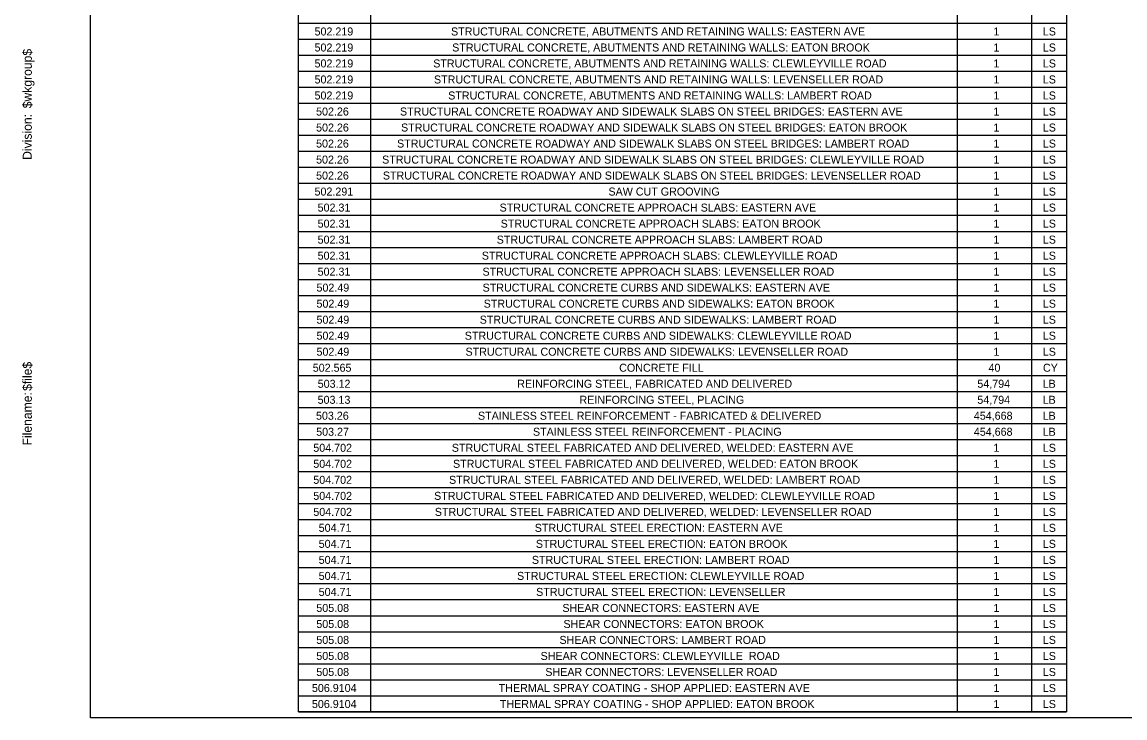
# Model space of a CAD drawing. Extents: x -18.7 to 5.6, y -2.7 to 4.
# Drawn here: x -9.864 to -8.508, y 2.235 to 3.09 of the extents above; entities that cross this region are included whole.
import ezdxf

# ---------------------------------------------------------------- set-up
doc = ezdxf.new("R2010")
doc.units = 0
doc.layers.add('ANNOTATION', color=7, linetype='Continuous')
doc.layers.add('BORDER', color=7, linetype='Continuous')

msp = doc.modelspace()

# ---------------------------------------------------------------- linework, layer by layer
at = {"layer": 'BORDER'}
for p, q in [((-9.4355, 3.9551), (-9.4355, 2.2424)), ((-8.7141, 3.9551), (-8.7141, 2.2424)), ((-8.6227, 3.9551), (-8.6227, 2.2424)), ((-9.524, 3.0889), (-8.5798, 3.0889)), ((-9.524, 3.0692), (-8.5798, 3.0692)), ((-9.524, 3.0495), (-8.5798, 3.0495)), ((-9.524, 3.0299), (-8.5798, 3.0299)), ((-9.524, 3.0102), (-8.5798, 3.0102)), ((-9.524, 2.9905), (-8.5798, 2.9905)), ((-9.524, 2.9708), (-8.5798, 2.9708)), ((-9.524, 2.9511), (-8.5798, 2.9511)), ((-9.524, 2.9314), (-8.5798, 2.9314)), ((-9.524, 2.9117), (-8.5798, 2.9117)), ((-9.524, 2.8921), (-8.5798, 2.8921)), ((-9.524, 2.8724), (-8.5798, 2.8724)), ((-9.524, 2.8527), (-8.5798, 2.8527)), ((-9.524, 2.833), (-8.5798, 2.833)), ((-9.524, 2.8133), (-8.5798, 2.8133)), ((-9.524, 2.7936), (-8.5798, 2.7936)), ((-9.524, 2.7739), (-8.5798, 2.7739)), ((-9.524, 2.7543), (-8.5798, 2.7543)), ((-9.524, 2.7346), (-8.5798, 2.7346)), ((-9.524, 2.7149), (-8.5798, 2.7149)), ((-9.524, 2.6952), (-8.5798, 2.6952)), ((-9.524, 2.6755), (-8.5798, 2.6755)), ((-9.524, 2.6558), (-8.5798, 2.6558)), ((-9.524, 2.6361), (-8.5798, 2.6361)), ((-9.524, 2.6165), (-8.5798, 2.6165)), ((-9.524, 2.5968), (-8.5798, 2.5968)), ((-9.524, 2.5771), (-8.5798, 2.5771)), ((-9.524, 2.5574), (-8.5798, 2.5574)), ((-9.524, 2.5377), (-8.5798, 2.5377)), ((-9.524, 2.518), (-8.5798, 2.518)), ((-9.524, 2.4983), (-8.5798, 2.4983)), ((-9.524, 2.4787), (-8.5798, 2.4787)), ((-9.524, 2.459), (-8.5798, 2.459)), ((-9.524, 2.4393), (-8.5798, 2.4393)), ((-9.524, 2.4196), (-8.5798, 2.4196)), ((-9.524, 2.3999), (-8.5798, 2.3999)), ((-9.524, 2.3802), (-8.5798, 2.3802)), ((-9.524, 2.3605), (-8.5798, 2.3605)), ((-9.524, 2.3408), (-8.5798, 2.3408)), ((-9.524, 2.3212), (-8.5798, 2.3212)), ((-9.524, 2.3015), (-8.5798, 2.3015)), ((-9.524, 2.2818), (-8.5798, 2.2818)), ((-9.524, 2.2621), (-8.5798, 2.2621)), ((-9.524, 2.2424), (-8.5798, 2.2424))]:
    msp.add_line(p, q, dxfattribs=at)
for points in [[(-9.7797, 3.9848), (-7.1131, 3.9848), (-7.1131, 2.2348), (-9.7797, 2.2348)], [(-9.524, 3.9748), (-8.5798, 3.9748), (-8.5798, 2.2424), (-9.524, 2.2424)]]:
    msp.add_lwpolyline(points, close=True, dxfattribs=at)

# ---------------------------------------------------------------- texts
at = {"layer": 'ANNOTATION'}
for s, height, p in [('502.219', 0.00984, (-9.5041, 3.0738)), ('STRUCTURAL CONCRETE, ABUTMENTS AND RETAINING WALLS: EASTERN AVE', 0.009843, (-9.3363, 3.0738)), ('1', 0.00984, (-8.6695, 3.0738)), ('LS', 0.00984, (-8.6088, 3.0738)), ('502.219', 0.00984, (-9.5041, 3.0541)), ('STRUCTURAL CONCRETE, ABUTMENTS AND RETAINING WALLS: EATON BROOK', 0.009843, (-9.3349, 3.0541)), ('LS', 0.00984, (-8.6088, 3.0541)), ('1', 0.00984, (-8.6695, 3.0541)), ('502.219', 0.00984, (-9.5041, 3.0345)), ('STRUCTURAL CONCRETE, ABUTMENTS AND RETAINING WALLS: CLEWLEYVILLE ROAD', 0.009843, (-9.3582, 3.0345)), ('1', 0.00984, (-8.6695, 3.0345)), ('LS', 0.00984, (-8.6088, 3.0345)), ('502.219', 0.00984, (-9.5041, 3.0148)), ('STRUCTURAL CONCRETE, ABUTMENTS AND RETAINING WALLS: LEVENSELLER ROAD', 0.009843, (-9.3573, 3.0148)), ('1', 0.00984, (-8.6695, 3.0148)), ('LS', 0.00984, (-8.6088, 3.0148)), ('502.219', 0.00984, (-9.5041, 2.9951)), ('STRUCTURAL CONCRETE, ABUTMENTS AND RETAINING WALLS: LAMBERT ROAD', 0.009843, (-9.3398, 2.9951)), ('1', 0.00984, (-8.6695, 2.9951)), ('LS', 0.00984, (-8.6088, 2.9951)), ('502.26', 0.00984, (-9.5022, 2.9754)), ('STRUCTURAL CONCRETE ROADWAY AND SIDEWALK SLABS ON STEEL BRIDGES: EASTERN AVE', 0.009843, (-9.3991, 2.9754)), ('1', 0.00984, (-8.6695, 2.9754)), ('LS', 0.00984, (-8.6088, 2.9754)), ('502.26', 0.00984, (-9.5022, 2.9557)), ('STRUCTURAL CONCRETE ROADWAY AND SIDEWALK SLABS ON STEEL BRIDGES: EATON BROOK', 0.009843, (-9.3978, 2.9557)), ('1', 0.00984, (-8.6695, 2.9557)), ('LS', 0.00984, (-8.6088, 2.9557)), ('502.26', 0.00984, (-9.5022, 2.936)), ('STRUCTURAL CONCRETE ROADWAY AND SIDEWALK SLABS ON STEEL BRIDGES: LAMBERT ROAD', 0.009843, (-9.4027, 2.936)), ('1', 0.00984, (-8.6695, 2.936)), ('LS', 0.00984, (-8.6088, 2.936)), ('502.26', 0.00984, (-9.5022, 2.9163)), ('STRUCTURAL CONCRETE ROADWAY AND SIDEWALK SLABS ON STEEL BRIDGES: CLEWLEYVILLE ROAD', 0.009843, (-9.421, 2.9163)), ('1', 0.00984, (-8.6695, 2.9163)), ('LS', 0.00984, (-8.6088, 2.9163)), ('502.26', 0.00984, (-9.5022, 2.8967)), ('STRUCTURAL CONCRETE ROADWAY AND SIDEWALK SLABS ON STEEL BRIDGES: LEVENSELLER ROAD', 0.009843, (-9.4201, 2.8967)), ('1', 0.00984, (-8.6695, 2.8967)), ('LS', 0.00984, (-8.6088, 2.8967)), ('502.291', 0.00984, (-9.5041, 2.877)), ('SAW CUT GROOVING', 0.009843, (-9.1428, 2.877)), ('1', 0.00984, (-8.6695, 2.877)), ('LS', 0.00984, (-8.6088, 2.877)), ('502.31', 0.00984, (-9.5003, 2.8573)), ('STRUCTURAL CONCRETE APPROACH SLABS: EASTERN AVE', 0.009843, (-9.2766, 2.8573)), ('1', 0.00984, (-8.6695, 2.8573)), ('LS', 0.00984, (-8.6088, 2.8573)), ('502.31', 0.00984, (-9.5003, 2.8376)), ('STRUCTURAL CONCRETE APPROACH SLABS: EATON BROOK', 0.009843, (-9.2753, 2.8376)), ('1', 0.00984, (-8.6695, 2.8376)), ('LS', 0.00984, (-8.6088, 2.8376)), ('502.31', 0.00984, (-9.5003, 2.8179)), ('STRUCTURAL CONCRETE APPROACH SLABS: LAMBERT ROAD', 0.009843, (-9.2802, 2.8179)), ('1', 0.00984, (-8.6695, 2.8179)), ('LS', 0.00984, (-8.6088, 2.8179)), ('502.31', 0.00984, (-9.5003, 2.7982)), ('STRUCTURAL CONCRETE APPROACH SLABS: CLEWLEYVILLE ROAD', 0.009843, (-9.2985, 2.7982)), ('1', 0.00984, (-8.6695, 2.7982)), ('LS', 0.00984, (-8.6088, 2.7982)), ('502.31', 0.00984, (-9.5003, 2.7785)), ('STRUCTURAL CONCRETE APPROACH SLABS: LEVENSELLER ROAD', 0.009843, (-9.2976, 2.7785)), ('1', 0.00984, (-8.6695, 2.7785)), ('LS', 0.00984, (-8.6088, 2.7785)), ('502.49', 0.00984, (-9.5017, 2.7589)), ('STRUCTURAL CONCRETE CURBS AND SIDEWALKS: EASTERN AVE', 0.009843, (-9.2975, 2.7589)), ('1', 0.00984, (-8.6695, 2.7589)), ('LS', 0.00984, (-8.6088, 2.7589)), ('502.49', 0.00984, (-9.5017, 2.7392)), ('STRUCTURAL CONCRETE CURBS AND SIDEWALKS: EATON BROOK', 0.009843, (-9.2962, 2.7392)), ('1', 0.00984, (-8.6695, 2.7392)), ('LS', 0.00984, (-8.6088, 2.7392)), ('502.49', 0.00984, (-9.5017, 2.7195)), ('STRUCTURAL CONCRETE CURBS AND SIDEWALKS: LAMBERT ROAD', 0.009843, (-9.3011, 2.7195)), ('1', 0.00984, (-8.6695, 2.7195)), ('LS', 0.00984, (-8.6088, 2.7195)), ('502.49', 0.00984, (-9.5017, 2.6998)), ('STRUCTURAL CONCRETE CURBS AND SIDEWALKS: CLEWLEYVILLE ROAD', 0.009843, (-9.3194, 2.6998)), ('1', 0.00984, (-8.6695, 2.6998)), ('LS', 0.00984, (-8.6088, 2.6998)), ('502.49', 0.00984, (-9.5017, 2.6801)), ('STRUCTURAL CONCRETE CURBS AND SIDEWALKS: LEVENSELLER ROAD', 0.009843, (-9.3185, 2.6801)), ('1', 0.00984, (-8.6695, 2.6801)), ('LS', 0.00984, (-8.6088, 2.6801)), ('502.565', 0.00984, (-9.5063, 2.6604)), ('CONCRETE FILL', 0.009843, (-9.1296, 2.6604)), ('40', 0.00984, (-8.6756, 2.6604)), ('CY', 0.00984, (-8.6086, 2.6604)), ('503.12', 0.00984, (-9.5002, 2.6407)), ('REINFORCING STEEL, FABRICATED AND DELIVERED', 0.009843, (-9.2549, 2.6407)), ('54,794', 0.00984, (-8.6893, 2.6407)), ('LB', 0.00984, (-8.609, 2.6407)), ('503.13', 0.00984, (-9.5003, 2.621)), ('REINFORCING STEEL, PLACING', 0.009843, (-9.1784, 2.621)), ('54,794', 0.00984, (-8.6893, 2.621)), ('LB', 0.00984, (-8.609, 2.621)), ('503.26', 0.00984, (-9.5023, 2.6014)), ('STAINLESS STEEL REINFORCEMENT - FABRICATED & DELIVERED', 0.009843, (-9.3032, 2.6014)), ('454,668', 0.00984, (-8.6936, 2.6014)), ('LB', 0.00984, (-8.609, 2.6014)), ('503.27', 0.00984, (-9.5021, 2.5817)), ('STAINLESS STEEL REINFORCEMENT - PLACING', 0.009843, (-9.2356, 2.5817)), ('454,668', 0.00984, (-8.6936, 2.5817)), ('LB', 0.00984, (-8.609, 2.5817)), ('504.702', 0.00984, (-9.5056, 2.562)), ('STRUCTURAL STEEL FABRICATED AND DELIVERED, WELDED: EASTERN AVE', 0.009843, (-9.3353, 2.562)), ('1', 0.00984, (-8.6695, 2.562)), ('LS', 0.00984, (-8.6088, 2.562)), ('504.702', 0.00984, (-9.5056, 2.5423)), ('STRUCTURAL STEEL FABRICATED AND DELIVERED, WELDED: EATON BROOK', 0.009843, (-9.3339, 2.5423)), ('1', 0.00984, (-8.6695, 2.5423)), ('LS', 0.00984, (-8.6088, 2.5423)), ('504.702', 0.00984, (-9.5056, 2.5226)), ('STRUCTURAL STEEL FABRICATED AND DELIVERED, WELDED: LAMBERT ROAD', 0.009843, (-9.3388, 2.5226)), ('1', 0.00984, (-8.6695, 2.5226)), ('LS', 0.00984, (-8.6088, 2.5226)), ('504.702', 0.00984, (-9.5056, 2.5029)), ('STRUCTURAL STEEL FABRICATED AND DELIVERED, WELDED: CLEWLEYVILLE ROAD', 0.009843, (-9.3571, 2.5029)), ('1', 0.00984, (-8.6695, 2.5029)), ('LS', 0.00984, (-8.6088, 2.5029)), ('504.702', 0.00984, (-9.5056, 2.4832)), ('STRUCTURAL STEEL FABRICATED AND DELIVERED, WELDED: LEVENSELLER ROAD', 0.009843, (-9.3562, 2.4832)), ('1', 0.00984, (-8.6695, 2.4832)), ('LS', 0.00984, (-8.6088, 2.4832)), ('504.71', 0.00984, (-9.499, 2.4636)), ('STRUCTURAL STEEL ERECTION: EASTERN AVE', 0.009843, (-9.2334, 2.4636)), ('1', 0.00984, (-8.6695, 2.4636)), ('LS', 0.00984, (-8.6088, 2.4636)), ('504.71', 0.00984, (-9.499, 2.4439)), ('STRUCTURAL STEEL ERECTION: EATON BROOK', 0.009843, (-9.232, 2.4439)), ('1', 0.00984, (-8.6695, 2.4439)), ('LS', 0.00984, (-8.6088, 2.4439)), ('504.71', 0.00984, (-9.499, 2.4242)), ('STRUCTURAL STEEL ERECTION: LAMBERT ROAD', 0.009843, (-9.2369, 2.4242)), ('1', 0.00984, (-8.6695, 2.4242)), ('LS', 0.00984, (-8.6088, 2.4242)), ('504.71', 0.00984, (-9.499, 2.4045)), ('STRUCTURAL STEEL ERECTION: CLEWLEYVILLE ROAD', 0.009843, (-9.2552, 2.4045)), ('1', 0.00984, (-8.6695, 2.4045)), ('LS', 0.00984, (-8.6088, 2.4045)), ('504.71', 0.00984, (-9.499, 2.3848)), ('STRUCTURAL STEEL ERECTION: LEVENSELLER', 0.009843, (-9.2317, 2.3848)), ('1', 0.00984, (-8.6695, 2.3848)), ('LS', 0.00984, (-8.6088, 2.3848)), ('505.08', 0.00984, (-9.5019, 2.3651)), ('SHEAR CONNECTORS: EASTERN AVE', 0.009843, (-9.1994, 2.3651)), ('1', 0.00984, (-8.6695, 2.3651)), ('LS', 0.00984, (-8.6088, 2.3651)), ('505.08', 0.00984, (-9.5019, 2.3454)), ('SHEAR CONNECTORS: EATON BROOK', 0.009843, (-9.1981, 2.3454)), ('1', 0.00984, (-8.6695, 2.3454)), ('LS', 0.00984, (-8.6088, 2.3454)), ('505.08', 0.00984, (-9.5019, 2.3258)), ('SHEAR CONNECTORS: LAMBERT ROAD', 0.009843, (-9.203, 2.3258)), ('1', 0.00984, (-8.6695, 2.3258)), ('LS', 0.00984, (-8.6088, 2.3258)), ('505.08', 0.00984, (-9.5019, 2.3061)), ('SHEAR CONNECTORS: CLEWLEYVILLE  ROAD', 0.009843, (-9.2262, 2.3061)), ('1', 0.00984, (-8.6695, 2.3061)), ('LS', 0.00984, (-8.6088, 2.3061)), ('505.08', 0.00984, (-9.5019, 2.2864)), ('SHEAR CONNECTORS: LEVENSELLER ROAD', 0.009843, (-9.2204, 2.2864)), ('1', 0.00984, (-8.6695, 2.2864)), ('LS', 0.00984, (-8.6088, 2.2864)), ('506.9104', 0.00984, (-9.5073, 2.2667)), ('THERMAL SPRAY COATING - SHOP APPLIED: EASTERN AVE', 0.009843, (-9.2777, 2.2667)), ('1', 0.00984, (-8.6695, 2.2667)), ('LS', 0.00984, (-8.6088, 2.2667)), ('506.9104', 0.00984, (-9.5073, 2.247)), ('THERMAL SPRAY COATING - SHOP APPLIED: EATON BROOK', 0.009843, (-9.2763, 2.247)), ('1', 0.00984, (-8.6695, 2.247)), ('LS', 0.00984, (-8.6088, 2.247))]:
    msp.add_text(s, height=height, dxfattribs=at).set_placement(p)
at = {"layer": 'BORDER'}
for s, p in [('$wkgroup$', (-9.8517, 2.9843)), ('Division:', (-9.8517, 2.9209)), ('$file$', (-9.8517, 2.6369)), ('Filename:', (-9.8517, 2.5698))]:
    msp.add_text(s, height=0.01116, rotation=90, dxfattribs=at).set_placement(p)

doc.saveas('drawing.dxf')
